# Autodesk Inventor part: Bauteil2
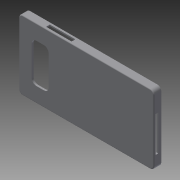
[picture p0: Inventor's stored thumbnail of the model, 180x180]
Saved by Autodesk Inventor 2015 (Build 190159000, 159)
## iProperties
Created: 2016-07
Part Number: Bauteil2
Material: Generisch
Document SubType Name: Modeling
Designer: pichl
Density: 1 g/cm^3
Appearance: Vorgabe
Author: pichl
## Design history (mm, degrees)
sketch "Skizze1"
  geometry: L1 (0, 0)-(143, 0); L2 (143, 0)-(143, -73.5); L3 (143, -73.5)-(0, -73.5); L4 (0, -73.5)-(0, 0); L5 (2, -1.5)-(141, -1.5); L6 (141, -1.5)-(141, -71.5); L7 (141, -71.5)-(2, -71.5); L8 (2, -71.5)-(2, -1.5); L9 (0, 0)-(143, 0); L10 (143, 0)-(143, -73.5); L11 (143, -73.5)-(0, -73.5); L12 (0, -73.5)-(0, 0); 2 further points
  constraints: 24 end point, 6 parallel, 3 horizontal, 3 perpendicular, 2 coincident
  dimensions: "d2" = 143 distance of L2.end L3.end; "d3" = 73.5 distance of L1.end L2.end; "d4" = 139 distance of L6.end L7.end; "d5" = 70 distance of L5.end L6.end; "d6" = 143 distance of L10.end L11.end; "d7" = 73.5 distance of L9.end L10.end
sketch "Skizze2"
  geometry: L1 (2, -1.5)-(141, -1.5); L2 (141, -1.5)-(141, -71.5); L3 (141, -71.5)-(2, -71.5); L4 (2, -71.5)-(2, -1.5); 1 further point
  constraints: 8 end point, 2 parallel, 1 horizontal, 1 perpendicular
  dimensions: "d8" = 139 distance of L2.end L3.end; "d9" = 70 distance of L1.end L2.end
extrude "Extrusion1" new body sketch "Skizze1" distance "d10" = 8; taper "d11" = 0 deg
extrude "Extrusion2" join sketch "Skizze2" distance "d12" = 2; taper "d13" = 0 deg
fillet "Rundung1" dims "d14" = 4
fillet "Rundung2" dims "d15" = 4
fillet "Rundung3" dims "d16" = 4
fillet "Rundung4" dims "d17" = 4
fillet "Rundung5" dims "d18" = 4
fillet "Rundung6" dims "d19" = 4
fillet "Rundung7" dims "d20" = 4
fillet "Rundung8" dims "d21" = 4
fillet "Rundung9" dims "d22" = 1
sketch "Skizze3"
  geometry: 1 further point
sketch "Skizze4"
  geometry: L1 (-116.3, 16)-(-124.3, 16); L2 (-129.3, 21)-(-129.3, 52.5); L3 (-124.3, 57.5)-(-116.3, 57.5); L4 (-111.3, 52.5)-(-111.3, 21); A1 r 5 centre (-124.3, 21) between (-129.3, 21) and (-124.3, 16); A2 r 5 centre (-124.3, 52.5) between (-124.3, 57.5) and (-129.3, 52.5); A3 r 5 centre (-116.3, 52.5) between (-111.3, 52.5) and (-116.3, 57.5); A4 r 5 centre (-116.3, 21) between (-116.3, 16) and (-111.3, 21); 1 further point
  constraints: 8 end point, 8 point on circle, 8 tangent, 4 centre point, 3 equal radius, 2 parallel, 1 horizontal, 1 perpendicular
  dimensions: "d23" = 5 radius of A1; "d34" = 31.5 distance of L4.start L4.end; "d35" = 8 distance of L3.start L3.end
extrude "Extrusion3" cut sketch "Skizze4" distance "d24" = 2; taper "d25" = 0 deg
sketch "Skizze5"
  geometry: L1 (133, -6)-(2, -6) reference; L2 (50, -2)-(23, -2); L3 (23, -2)-(23, -6); L4 (23, -6)-(50, -6); L5 (50, -6)-(50, -2); 2 further points
  constraints: 8 end point, 2 parallel, 1 horizontal, 1 perpendicular, 1 point on line
  dimensions: "d36" = 27 distance of L2.start L2.end; "d37" = 4 distance of L4.end L2.start
extrude "Extrusion4" cut sketch "Skizze5" distance "d26" = 2; taper "d27" = 0 deg
sketch "Skizze6"
  geometry: L1 (85, -6)-(112, -6) reference; L2 (83.033, -2)-(101.033, -2); L3 (101.033, -2)-(101.033, -6); L4 (101.033, -6)-(83.033, -6); L5 (83.033, -6)-(83.033, -2); 2 further points
  constraints: 8 end point, 2 parallel, 1 horizontal, 1 perpendicular, 1 point on line
  dimensions: "d32" = 18 distance of L2.start L2.end; "d33" = 4 distance of L2.end L3.end
extrude "Extrusion5" cut sketch "Skizze6" distance "d28" = 2; taper "d29" = 0 deg
sketch "Skizze7"
  geometry: L1 (63.5, -6)-(1.5, -6) reference; L2 (18, -3.188)-(55.5, -3.188); L3 (55.5, -3.188)-(55.5, -6); L4 (55.5, -6)-(18, -6); L5 (18, -6)-(18, -3.188); 2 further points
  constraints: 8 end point, 2 parallel, 1 horizontal, 1 perpendicular, 1 point on line
extrude "Extrusion6" cut sketch "Skizze7" distance "d30" = 2; taper "d31" = 0 deg
workpoint "Arbeitspunkt1"
workpoint "Arbeitspunkt2"
workpoint "Arbeitspunkt3"
node "Volumenkörper1"
